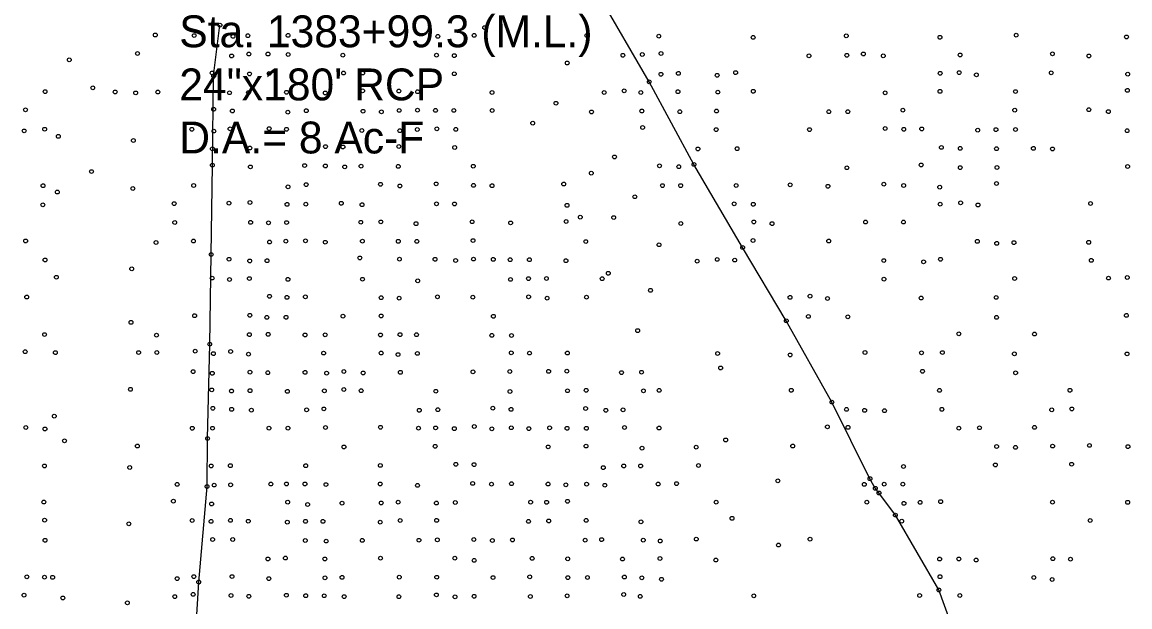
# Model space of a CAD drawing. Extents: x 20503438 to 20508873, y 7964251 to 7984667.
# Drawn here: x 20506686 to 20507270, y 7970876 to 7971184 of the extents above; entities that cross this region are included whole.
import ezdxf

# ---------------------------------------------------------------- set-up
doc = ezdxf.new("R2010")
doc.units = 0
for name, color, linetype in [('SurDrainageArrowDown', 7, 'Continuous'), ('SurSurveyPoints', 7, 'Continuous'), ('SurTxtDrainage', 7, 'Continuous')]:
    doc.layers.add(name, color=color, linetype=linetype)

msp = doc.modelspace()

# ---------------------------------------------------------------- linework, layer by layer
at = {"layer": 'SurDrainageArrowDown'}
for points in [[(20507224.7, 7970759.18), (20507204.45, 7970804.1), (20507184.9, 7970841.74), (20507169.23, 7970884.93), (20507146.3, 7970924.33), (20507137.63, 7970936.09), (20507135.68, 7970938.54), (20507132.89, 7970943.61), (20507112.81, 7970984), (20507088.76, 7971026.9), (20507065.73, 7971065.56), (20507040.06, 7971109.35), (20507016.49, 7971152.89), (20506989.99, 7971198.73)], [(20506758.23, 7970612.66), (20506759.96, 7970618.07), (20506766.03, 7970640.28), (20506769.58, 7970650.69), (20506772.91, 7970661.98), (20506773.11, 7970678.32), (20506770.25, 7970703.37), (20506769.67, 7970724.66), (20506772.21, 7970747.11), (20506774.83, 7970769.77), (20506774.2, 7970791.54), (20506775.89, 7970837.25), (20506778.93, 7970889.1), (20506783.31, 7970939.45), (20506783.6, 7970964.79), (20506784.75, 7971014.54), (20506785.47, 7971061.82), (20506786.12, 7971108.98), (20506786.8, 7971156.01), (20506790.11, 7971182.82)]]:
    msp.add_lwpolyline(points, dxfattribs=at)
at = {"layer": 'SurSurveyPoints'}
for centre in [(20506790.11, 7971182.82), (20506756.01, 7971177.62), (20506776.5, 7971177.31), (20506797.04, 7971176.91), (20506804.86, 7971177.26), (20506826.01, 7971177.4), (20506904.99, 7971176.9), (20506924.18, 7971177.43), (20506929.74, 7971181.51), (20506983.58, 7971177.33), (20507021.51, 7971176.99), (20507071.27, 7971176.38), (20507120.4, 7971177.19), (20507169.8, 7971176.42), (20507210.01, 7971177.55), (20507268.15, 7971176.57), (20506710.67, 7971164.55), (20506746.67, 7971167.83), (20506796.29, 7971166.56), (20506805.37, 7971167.58), (20506815.46, 7971167.58), (20506826.06, 7971167.31), (20506854.92, 7971166.99), (20506904.31, 7971166.95), (20506913.69, 7971166.75), (20507002.61, 7971166.91), (20507012.84, 7971167.33), (20507022.71, 7971167.84), (20507100.71, 7971166.65), (20507120.68, 7971166.93), (20507129.4, 7971167.63), (20507139.91, 7971166.65), (20507180.41, 7971167.1), (20507229.1, 7971167.66), (20507248.33, 7971166.55), (20506973.25, 7971162.85), (20506785.99, 7971157.6), (20506786.8, 7971156.01), (20506805.69, 7971157.09), (20506816.04, 7971157.35), (20506855.31, 7971157.56), (20506865.37, 7971157.55), (20506913.68, 7971157.17), (20507016.49, 7971152.89), (20507022.68, 7971156.91), (20507031.86, 7971157.38), (20507052.28, 7971156.35), (20507062.03, 7971157.76), (20507169.87, 7971157.41), (20507179.95, 7971157.79), (20507189.01, 7971156.61), (20507228.47, 7971157.69), (20507268.8, 7971156.99), (20506697.92, 7971147.74), (20506723.05, 7971149.78), (20506734.84, 7971147.58), (20506745.68, 7971147.07), (20506757.34, 7971147.55), (20506795.18, 7971147.15), (20506805.19, 7971147.21), (20506825.2, 7971147.39), (20506845.68, 7971147.06), (20506865.36, 7971148.19), (20506884.44, 7971148.06), (20506894.37, 7971147.69), (20506933.6, 7971147.3), (20506992.7, 7971147.27), (20507003.29, 7971148.16), (20507012.05, 7971147.31), (20507031.65, 7971147.72), (20507052.63, 7971147.5), (20507071.35, 7971147.93), (20507140.86, 7971147.14), (20507169.81, 7971147.87), (20507209.64, 7971147.78), (20507268.61, 7971148.4), (20506967.3, 7971141.62), (20506687.61, 7971138.15), (20506786.8, 7971138.43), (20506796.66, 7971137.56), (20506825.94, 7971136.95), (20506835.65, 7971137.68), (20506865.58, 7971137.4), (20506875.26, 7971137.07), (20506884.61, 7971137.83), (20506894.27, 7971137.96), (20506903.77, 7971137.86), (20506913.43, 7971137.84), (20506933.67, 7971137.81), (20506986.02, 7971137.03), (20507012.57, 7971137.53), (20507032.62, 7971137.14), (20507051.95, 7971137.52), (20507111.19, 7971137.14), (20507121.2, 7971137.15), (20507150.25, 7971137.99), (20507209.22, 7971137.94), (20507248.32, 7971138.23), (20507258.59, 7971137.21), (20506955.05, 7971131.12), (20506686.9, 7971127.03), (20506697.69, 7971127.91), (20506704.9, 7971124.15), (20506775.31, 7971127.87), (20506786.93, 7971126.93), (20506795.46, 7971128.11), (20506816.04, 7971128.24), (20506825.23, 7971127.87), (20506864.94, 7971127.27), (20506884.96, 7971127.15), (20506894.19, 7971127.77), (20506904.49, 7971128.14), (20506914.46, 7971127.83), (20507013.02, 7971128.81), (20507051.77, 7971127.7), (20507101.02, 7971127.7), (20507140.92, 7971128.27), (20507150.7, 7971127.9), (20507160.18, 7971128.08), (20507189.69, 7971127.41), (20507199.3, 7971127.71), (20507209.64, 7971127.8), (20507268.47, 7971127.12), (20506744.47, 7971121.99), (20506786.14, 7971117.58), (20506805.85, 7971118.01), (20506845.81, 7971118.73), (20506854.98, 7971118.58), (20506884.46, 7971118.78), (20506913.89, 7971118.26), (20507062.82, 7971117.67), (20507170.55, 7971118.32), (20507180.48, 7971117.83), (20507199.58, 7971117.64), (20507219.05, 7971117.82), (20506998.15, 7971113.28), (20507042.16, 7971117.53), (20507229.11, 7971117.51), (20506786.12, 7971108.98), (20506806.17, 7971108.05), (20506834.76, 7971108.75), (20506845.7, 7971108.56), (20506855.89, 7971108.04), (20506864.54, 7971108.44), (20506884.16, 7971108.31), (20506923.7, 7971108.4), (20507021.91, 7971108.58), (20507032.05, 7971108.16), (20507040.06, 7971109.35), (20507120.72, 7971107.6), (20507159.85, 7971109.07), (20507180.49, 7971107.66), (20507199.84, 7971107.71), (20507268.74, 7971108.23), (20506722.41, 7971105.59), (20506985.94, 7971104.75), (20506696.85, 7971098.13), (20506704.37, 7971094.77), (20506744.17, 7971096.69), (20506776.26, 7971098.26), (20506826.01, 7971097.56), (20506835.56, 7971098.71), (20506874.76, 7971098.89), (20506885.01, 7971098), (20506904.11, 7971099.08), (20506923.84, 7971098.31), (20506933.61, 7971098.13), (20506971.4, 7971099.02), (20507023.44, 7971098.19), (20507033.06, 7971098.19), (20507062.3, 7971098.23), (20507090.82, 7971098.62), (20507110.73, 7971097.84), (20507140.22, 7971098.96), (20507150.65, 7971098.26), (20507169.66, 7971097.33), (20507199.58, 7971099.3), (20506766.01, 7971088.67), (20506794.88, 7971088.89), (20506805.96, 7971089.29), (20506835.38, 7971088.42), (20506854.09, 7971088.85), (20506904.34, 7971088.6), (20506913.79, 7971088.49), (20507008.91, 7971092.3), (20507061.3, 7971088.54), (20507169.9, 7971088.39), (20507180.68, 7971089.13), (20507249.21, 7971088.73), (20506696.7, 7971088.03), (20506825.5, 7971088.28), (20506865.05, 7971088.1), (20506973.15, 7971087.78), (20507071.36, 7971088.33), (20507189.85, 7971087.99), (20506766.28, 7971078.75), (20506806.28, 7971078.78), (20506815.7, 7971078.54), (20506825.26, 7971078.69), (20506864.37, 7971078.86), (20506874.95, 7971079.04), (20506893.53, 7971078.11), (20506923.08, 7971079.12), (20506943.4, 7971078.51), (20506972.64, 7971079.25), (20506980.14, 7971081.53), (20506997.76, 7971081.32), (20507033.18, 7971078.2), (20507071.67, 7971079.03), (20507081.24, 7971078.14), (20507130.57, 7971078.97), (20507150.53, 7971078.95), (20506687.65, 7971069), (20506756.42, 7971068.15), (20506776.14, 7971068.96), (20506816.29, 7971068.43), (20506824.87, 7971068.9), (20506835.24, 7971069.06), (20506845.65, 7971068.31), (20506865.24, 7971068.91), (20506884.17, 7971068.79), (20506893.94, 7971068.76), (20506923.57, 7971069.19), (20506983.02, 7971068.66), (20507021.67, 7971066.98), (20507065.73, 7971065.56), (20507071.23, 7971069.24), (20507111.13, 7971068.94), (20507189.5, 7971068.77), (20507199.72, 7971067.7), (20507208.8, 7971068.12), (20507248.23, 7971068.26), (20506785.47, 7971061.82), (20506794.91, 7971059.34), (20506863.85, 7971060.04), (20506884.76, 7971059.36), (20506903.54, 7971059.31), (20506923.85, 7971059.42), (20506934.25, 7971059.26), (20507052.35, 7971059.25), (20507170.07, 7971059.31), (20506697.91, 7971058.97), (20506743.58, 7971054.27), (20506805.81, 7971058.46), (20506814.94, 7971058.57), (20506914.41, 7971058.67), (20506943.15, 7971059.11), (20506953.3, 7971059.1), (20506972.57, 7971058.57), (20507041.77, 7971058.34), (20507061.57, 7971058.9), (20507140.16, 7971058.64), (20507161.16, 7971058), (20507249.59, 7971058.75), (20506703.86, 7971049.85), (20506786.03, 7971049.4), (20506795.15, 7971048.67), (20506805.64, 7971049.15), (20506825.97, 7971048.74), (20506865.28, 7971048.8), (20506894.39, 7971047.97), (20506943.33, 7971048.7), (20506952.81, 7971049.11), (20506962.28, 7971049.21), (20506991.68, 7971049.07), (20506994.89, 7971051.95), (20507140.26, 7971048.86), (20507209.18, 7971049.2), (20507258.67, 7971049.4), (20507268.58, 7971049.71), (20507017.18, 7971042.95), (20506688.21, 7971039.4), (20506816.25, 7971039.8), (20506825.47, 7971039.24), (20506835.18, 7971039.55), (20506875.12, 7971039.05), (20506884.59, 7971038.81), (20506904.8, 7971039.52), (20506923.49, 7971039.32), (20506952.87, 7971039.52), (20506962.63, 7971038.79), (20506983.41, 7971039.37), (20507090.75, 7971039.22), (20507101.28, 7971039.88), (20507110.46, 7971038.64), (20507159.85, 7971038.88), (20507199.44, 7971039.2), (20506743.22, 7971026.05), (20506776.78, 7971029.57), (20506805.88, 7971029.77), (20506814.84, 7971028.68), (20506824.97, 7971028.71), (20506854.97, 7971029.29), (20506875.14, 7971029.44), (20506934.32, 7971029.24), (20507088.76, 7971026.9), (20507100.39, 7971029.18), (20507121.21, 7971028.96), (20507199.64, 7971028.67), (20507268.1, 7971029.72), (20506697.64, 7971019.61), (20506756.69, 7971019.29), (20506805.64, 7971019.6), (20506815.53, 7971019.74), (20506835, 7971019.42), (20506845.63, 7971019.48), (20506874.75, 7971019.42), (20506885.07, 7971019.6), (20506893.79, 7971019.53), (20506933.49, 7971019.2), (20506943.86, 7971019.11), (20507010.39, 7971021.7), (20507179.75, 7971019.99), (20507219.62, 7971019.89), (20506784.75, 7971014.54), (20506687.41, 7971010.56), (20506703.34, 7971010.08), (20506747.23, 7971010.12), (20506756.87, 7971010.15), (20506777.09, 7971010.83), (20506786.64, 7971009.56), (20506795.76, 7971010.66), (20506805.2, 7971009.3), (20506844.78, 7971009.85), (20506875.13, 7971009.87), (20506884.02, 7971009.06), (20506894.24, 7971009.67), (20506943.73, 7971010.01), (20506953.37, 7971009.85), (20506973.34, 7971009.87), (20507052.53, 7971009.64), (20507090.76, 7971008.88), (20507130.26, 7971010.18), (20507160.05, 7971009.95), (20507171.08, 7971010.12), (20507209.04, 7971009.44), (20507268.43, 7971009.41), (20507054.15, 7971002), (20506775.96, 7971000.08), (20506786.07, 7970999.2), (20506805.94, 7970999.78), (20506815.33, 7970999.48), (20506835.01, 7970999.68), (20506846.36, 7970999.24), (20506855.49, 7971000.11), (20506865.63, 7970999.35), (20506885.25, 7970999.7), (20506923.54, 7970999.98), (20506942.97, 7971000.11), (20506963.42, 7971000.2), (20506973.06, 7971000.29), (20507001.83, 7970999.54), (20507012.45, 7970999.74), (20507160.59, 7971000.24), (20507209.67, 7970999.44), (20506742.91, 7970990.73), (20506785.76, 7970990.43), (20506796.18, 7970989.85), (20506805.99, 7970990.03), (20506825.68, 7970989.64), (20506845.18, 7970989.95), (20506855.46, 7970990.62), (20506864.56, 7970990.02), (20506903.98, 7970989.73), (20506943.03, 7970989.56), (20506973.4, 7970989.98), (20506983.21, 7970990.21), (20507013.43, 7970989.95), (20507021.74, 7970990.19), (20507091.39, 7970990.24), (20507169.57, 7970990.19), (20507238.33, 7970990.23), (20507112.81, 7970984), (20506786.4, 7970980.75), (20506796.29, 7970980.18), (20506806.7, 7970979.76), (20506835.84, 7970979.93), (20506844.94, 7970980.41), (20506895.24, 7970979.69), (20506905.04, 7970979.99), (20506933.99, 7970980.82), (20506943.63, 7970980.15), (20506982.95, 7970980.6), (20506993.63, 7970979.66), (20507002.68, 7970979.95), (20507120.52, 7970980.14), (20507130.07, 7970979.62), (20507140.57, 7970979.45), (20507170.82, 7970980.18), (20507228.72, 7970979.93), (20507239.32, 7970980.4), (20506702.78, 7970976.59), (20506687.75, 7970970.61), (20506697.86, 7970969.84), (20506775.53, 7970970.2), (20506786.23, 7970970.21), (20506815.97, 7970970.28), (20506825.97, 7970970.26), (20506845.75, 7970970.63), (20506874.78, 7970970.73), (20506894.79, 7970970.24), (20506903.85, 7970970.38), (20506913.71, 7970970.01), (20506924.23, 7970971.12), (20506933.52, 7970969.93), (20506943.74, 7970970.47), (20506953.03, 7970970.02), (20506963.95, 7970970.45), (20506973.16, 7970970.19), (20506983.35, 7970970.18), (20507003.44, 7970970.62), (20507021.67, 7970970.33), (20507110.44, 7970970.96), (20507121.3, 7970970.66), (20507179.72, 7970970.28), (20507190.65, 7970970.46), (20507219.67, 7970970.68), (20506708.17, 7970963.6), (20506746.59, 7970960.81), (20506783.6, 7970964.79), (20506855.51, 7970960.34), (20506903.62, 7970960.69), (20506963.2, 7970960.37), (20506983.18, 7970960.79), (20507041.27, 7970960.24), (20507056.79, 7970964.03), (20507092.15, 7970960.81), (20507199.67, 7970960.57), (20507209.65, 7970960.11), (20507229.2, 7970960.8), (20507248.61, 7970961.15), (20507268.92, 7970960.51), (20507012.69, 7970959.72), (20506697.56, 7970950.32), (20506742.54, 7970949.49), (20506785.53, 7970950.33), (20506795.6, 7970950.47), (20506835.33, 7970950.46), (20506874.69, 7970950.6), (20506914.52, 7970951.18), (20506924.09, 7970951.04), (20506992.27, 7970949.43), (20507003.02, 7970950.33), (20507011.96, 7970950.31), (20507042.43, 7970950.54), (20507150.56, 7970950.01), (20507199.01, 7970950.86), (20507239.21, 7970951.22), (20507084.27, 7970942.48), (20507132.89, 7970943.61), (20506767.57, 7970940.62), (20506783.31, 7970939.45), (20506787.06, 7970940.23), (20506795.76, 7970940.34), (20506816.95, 7970940.78), (20506825.18, 7970940.82), (20506834.96, 7970940.82), (20506846, 7970940.5), (20506874.65, 7970940.81), (20506894.29, 7970940.06), (20506923.38, 7970941.1), (20506933.34, 7970940.68), (20506943.85, 7970940.95), (20506963.12, 7970940.76), (20506972.52, 7970940.35), (20506983.46, 7970940.7), (20506993.1, 7970940.14), (20507021.17, 7970940.79), (20507030.91, 7970941), (20507129.88, 7970940.62), (20507135.68, 7970938.54), (20507140.41, 7970940.7), (20507150.21, 7970940.69), (20506697.24, 7970931.3), (20506765.56, 7970931.76), (20506825.83, 7970931.23), (20506854.51, 7970930.66), (20506875.17, 7970930.79), (20506884.07, 7970931.25), (20506904.23, 7970930.74), (20506914.22, 7970931.02), (20506953.96, 7970931.23), (20506962.36, 7970931.14), (20506973.39, 7970931.68), (20507051.76, 7970931.19), (20507131.24, 7970931.23), (20507137.63, 7970936.09), (20507159.31, 7970931.1), (20507170.16, 7970931.5), (20507229.16, 7970931.22), (20507268.77, 7970931.13), (20506785.72, 7970930.27), (20506836.34, 7970929.99), (20507150.79, 7970930.59), (20506697.66, 7970921.72), (20506742.07, 7970919.76), (20506775.47, 7970921.54), (20506785.41, 7970921.07), (20506795.65, 7970921.62), (20506805.07, 7970921.16), (20506825.65, 7970920.65), (20506835.24, 7970921.11), (20506844.44, 7970921.1), (20506874.65, 7970920.64), (20506885.18, 7970921.56), (20506904.38, 7970921.62), (20506952.8, 7970921.1), (20506963.49, 7970921.32), (20506983.25, 7970921.6), (20507012.14, 7970920.87), (20507060.16, 7970922.69), (20507146.3, 7970924.33), (20507149.61, 7970921.19), (20507249.02, 7970921.54), (20506697.89, 7970911.1), (20506786.26, 7970911.52), (20506796.84, 7970911.54), (20506835.11, 7970911.01), (20506846.15, 7970910.69), (20506865.19, 7970911.05), (20506895.04, 7970911.14), (20506904.75, 7970911.32), (20506924, 7970911.5), (20506933.78, 7970911.03), (20506944.35, 7970911.29), (20506982.7, 7970911.19), (20506991.38, 7970911.45), (20507013.37, 7970911.16), (20507022.29, 7970910.74), (20507041.3, 7970911.74), (20507084.68, 7970908.59), (20507101.28, 7970911.73), (20506824.64, 7970901.73), (20506874.78, 7970901.67), (20506913.95, 7970901.65), (20506954.74, 7970901.59), (20507022.16, 7970901.48), (20506815.42, 7970901.25), (20506845.43, 7970901.28), (20506924.16, 7970900.5), (20506973.48, 7970901.32), (20507002.39, 7970901.22), (20507051.63, 7970900.68), (20507169.6, 7970901.23), (20507179.72, 7970901.25), (20507188.87, 7970900.69), (20507229.29, 7970901.4), (20507238.6, 7970901.15), (20506688.27, 7970891.85), (20506697.63, 7970891.65), (20506701.87, 7970891.57), (20506767.55, 7970890.88), (20506776.36, 7970891.95), (20506796.49, 7970891.98), (20506815.89, 7970890.88), (20506845.49, 7970891.33), (20506854.5, 7970891.55), (20506884.7, 7970891.65), (20506904.44, 7970891.62), (20506934.12, 7970891.45), (20506953.48, 7970891.86), (20506973.54, 7970891.42), (20506983.89, 7970891.49), (20507003.37, 7970891.73), (20507012.6, 7970891.31), (20507022.93, 7970890.55), (20507169.81, 7970891.89), (20507219.29, 7970891.5), (20507228.92, 7970890.42), (20506778.93, 7970889.1), (20507169.23, 7970884.93), (20506686.82, 7970882.18), (20506707.26, 7970880.68), (20506741.32, 7970878.14), (20506766.29, 7970881.4), (20506775.97, 7970882.6), (20506795.98, 7970881.99), (20506805.38, 7970881.58), (20506825.15, 7970882.13), (20506835.35, 7970881.89), (20506845.12, 7970881.85), (20506855.59, 7970881.41), (20506884.49, 7970881.34), (20506904.26, 7970882.3), (20506914.09, 7970881.28), (20506924.13, 7970881.59), (20506953.8, 7970881.47), (20506973.17, 7970881.83), (20507003.02, 7970882.52), (20507011.75, 7970881.54), (20507071.61, 7970881.8), (20507159.06, 7970882.02), (20507180.26, 7970882)]:
    msp.add_circle(centre, 1, dxfattribs=at)

# ---------------------------------------------------------------- texts
at = {"layer": 'SurTxtDrainage'}
for s, p in [('Sta. 1383+99.3 (M.L.)', (20506768.68, 7971171.15)), ('24"x180\' RCP', (20506768.68, 7971143.15)), ('D.A.= 8 Ac-F', (20506768.68, 7971115.15))]:
    msp.add_text(s, height=16.8, dxfattribs=at).set_placement(p)

doc.saveas('drawing.dxf')
